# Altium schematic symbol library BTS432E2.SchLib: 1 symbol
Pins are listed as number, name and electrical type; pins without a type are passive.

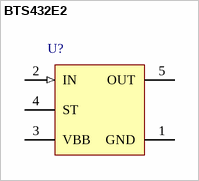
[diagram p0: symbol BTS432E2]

## BTS432E2
designator U?
Smart High-Side Power Switch, 1 Channel, 5 A Load Current, -40 to 150 degC, PG-TO220AB-5, Tube; Manufacturer: Infineon; PartNumber: BTS432E2; Channels: 1; Green: FALSE; Group: Automotive Qualified; Load Current (typ): 5 A; Recommended Operating Voltage Max.: 42 V; Recommended Operating Voltage Min.: 4.5 V; RON @ 25degreesC: 38 mOhm; RON(max) @ 150degreesC: 70 mOhm
footprint INF-PG-TO220AB-5 (FM, 5-Leads, Body 9.9x4.4mm, Pitch 1.7mm)
pins: 1 GND (power) "Logic ground", 2 IN (in) "Input, activates the power switch in case of logical high signal", 3 VBB (power) "Positive power supply voltage, the tab is shorted to this pin", 4 ST (oc) "Diagnostic feedback, low on failure", 5 OUT (power) "Output to the load"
